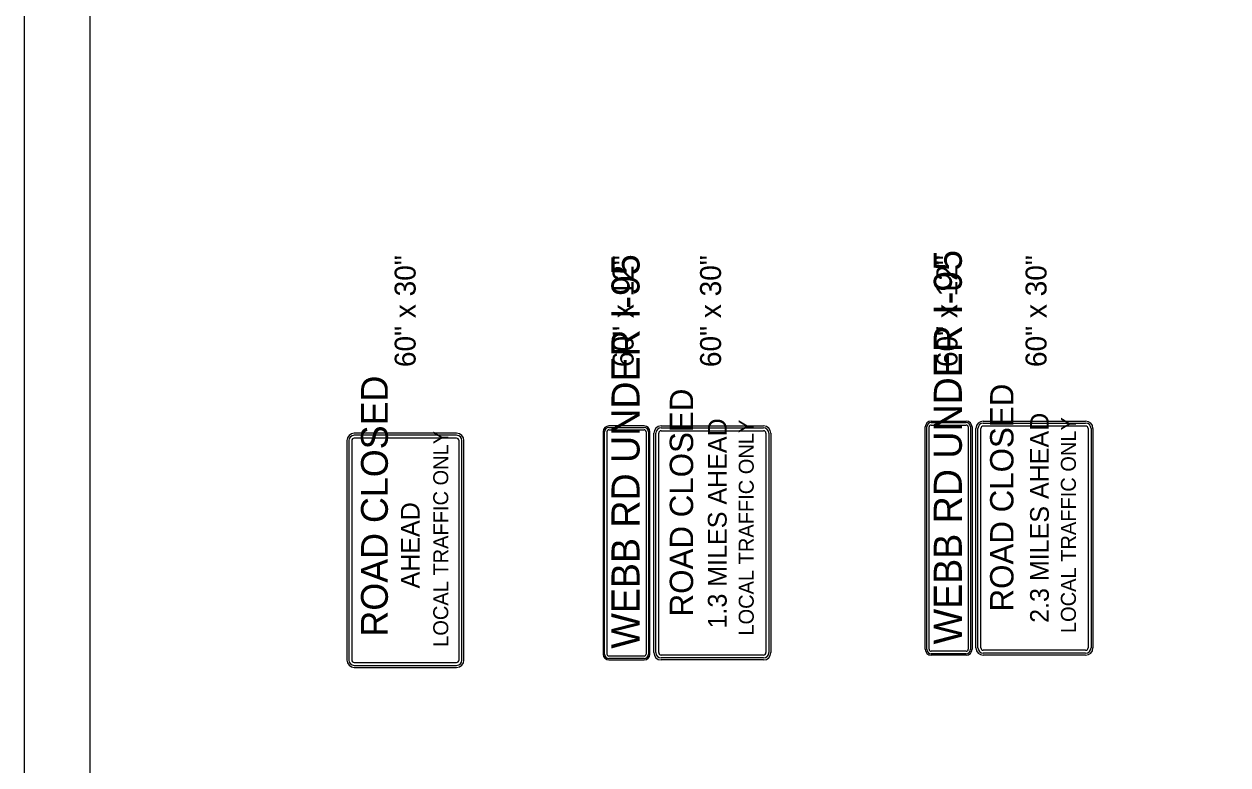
# Model space of a CAD drawing. Extents: x 1149904 to 1171904, y 589308 to 623636.
# Drawn here: x 1149904 to 1156977, y 601940 to 606292 of the extents above; entities that cross this region are included whole.
import ezdxf

# ---------------------------------------------------------------- set-up
doc = ezdxf.new("R2010")
doc.units = 0
for name, color, linetype in [('BORDER', 7, 'Continuous'), ('D_Text_Standard', 7, 'Continuous'), ('PLOT BOUNDARY', 7, 'Continuous'), ('SIGNS TRAFFIC', 7, 'Continuous')]:
    doc.layers.add(name, color=color, linetype=linetype)

msp = doc.modelspace()

# ---------------------------------------------------------------- linework, layer by layer
at = {"layer": 'BORDER'}
msp.add_lwpolyline([(1150292.4, 590926.2), (1150292.4, 622926.2), (1171292.4, 622926.2), (1171292.4, 590926.2)], close=True, dxfattribs=at)
at = {"layer": 'PLOT BOUNDARY'}
msp.add_lwpolyline([(1171904.3, 589307.6), (1171904.3, 623307.6), (1149904.3, 623307.6), (1149904.3, 589307.6)], close=True, dxfattribs=at)
at = {"layer": 'SIGNS TRAFFIC'}
for p, q in [((1155233.3, 603959.9), (1155439.5, 603959.9)), ((1155233.3, 603951.3), (1155439.5, 603951.3)), ((1155539.8, 603959.9), (1156141.3, 603959.9)), ((1152445.5, 603888.3), (1151843.9, 603888.3)), ((1153306.2, 603897.5), (1153306.2, 602591.2)), ((1153314.8, 602591.2), (1153314.8, 603897.5)), ((1153329.1, 602591.2), (1153329.1, 603897.5)), ((1153546.8, 603931.9), (1153340.5, 603931.9)), ((1153340.5, 603923.3), (1153546.8, 603923.3)), ((1153340.5, 603908.9), (1153546.8, 603908.9)), ((1153558.3, 603897.5), (1153558.3, 602591.2)), ((1153572.6, 603897.5), (1153572.6, 602591.2)), ((1153581.2, 602591.2), (1153581.2, 603897.5)), ((1153604.1, 602599.8), (1153604.1, 603888.9)), ((1153615.5, 602599.8), (1153615.5, 603888.9)), ((1153632.7, 602599.8), (1153632.7, 603888.9)), ((1153647.1, 603931.9), (1154248.6, 603931.9)), ((1153647.1, 603920.4), (1154248.6, 603920.4)), ((1153647.1, 603903.2), (1154248.6, 603903.2)), ((1154262.9, 603888.9), (1154262.9, 602599.8)), ((1154280.1, 603888.9), (1154280.1, 602599.8)), ((1154291.6, 603888.9), (1154291.6, 602599.8)), ((1155198.9, 602619.3), (1155198.9, 603925.5)), ((1155207.5, 602619.3), (1155207.5, 603925.5)), ((1155221.8, 602619.3), (1155221.8, 603925.5)), ((1155233.3, 603937), (1155439.5, 603937)), ((1155451, 603925.5), (1155451, 602619.3)), ((1155465.3, 603925.5), (1155465.3, 602619.3)), ((1155473.9, 603925.5), (1155473.9, 602619.3)), ((1155496.8, 602627.9), (1155496.8, 603916.9)), ((1155508.3, 602627.9), (1155508.3, 603916.9)), ((1155525.5, 602627.9), (1155525.5, 603916.9)), ((1155539.8, 603948.4), (1156141.3, 603948.4)), ((1155539.8, 603931.3), (1156141.3, 603931.3)), ((1156155.7, 603916.9), (1156155.7, 602627.9)), ((1156172.8, 603916.9), (1156172.8, 602627.9)), ((1156184.3, 603916.9), (1156184.3, 602627.9)), ((1151801, 603845.3), (1151801, 602556.3)), ((1151812.4, 603845.3), (1151812.4, 602556.3)), ((1151829.6, 603845.3), (1151829.6, 602556.3)), ((1152445.5, 603876.9), (1151843.9, 603876.9)), ((1152445.5, 603859.7), (1151843.9, 603859.7)), ((1152459.8, 602556.3), (1152459.8, 603845.3)), ((1152477, 602556.3), (1152477, 603845.3)), ((1152488.5, 602556.3), (1152488.5, 603845.3)), ((1155439.5, 602607.8), (1155233.3, 602607.8)), ((1156141.3, 602613.5), (1155539.8, 602613.5)), ((1151843.9, 602542), (1152445.5, 602542)), ((1153546.8, 602579.8), (1153340.5, 602579.8)), ((1153546.8, 602565.5), (1153340.5, 602565.5)), ((1153340.5, 602556.9), (1153546.8, 602556.9)), ((1154248.6, 602585.5), (1153647.1, 602585.5)), ((1154248.6, 602568.3), (1153647.1, 602568.3)), ((1154248.6, 602556.9), (1153647.1, 602556.9)), ((1155439.5, 602593.5), (1155233.3, 602593.5)), ((1155439.5, 602584.9), (1155233.3, 602584.9)), ((1156141.3, 602596.4), (1155539.8, 602596.4)), ((1156141.3, 602584.9), (1155539.8, 602584.9)), ((1151843.9, 602524.8), (1152445.5, 602524.8)), ((1151843.9, 602513.3), (1152445.5, 602513.3))]:
    msp.add_line(p, q, dxfattribs=at)
for centre, radius, start, end in [((1155233.3, 603925.5), 34.4, 90, 180), ((1155233.3, 603925.5), 25.8, 90, 180), ((1155439.5, 603925.5), 34.4, 0, 90), ((1155439.5, 603925.5), 25.8, 0, 90), ((1155539.8, 603916.9), 43, 90, 180), ((1156141.3, 603916.9), 43, 0, 90), ((1151843.9, 603845.3), 43, 90, 180), ((1152445.5, 603845.3), 43, 0, 90), ((1153340.5, 603897.5), 34.4, 90, 180), ((1153340.5, 603897.5), 25.8, 90, 180), ((1153340.5, 603897.5), 11.5, 90, 180), ((1153546.8, 603897.5), 34.4, 0, 90), ((1153546.8, 603897.5), 25.8, 0, 90), ((1153546.8, 603897.5), 11.5, 0, 90), ((1153647.1, 603888.9), 43, 90, 180), ((1153647.1, 603888.9), 31.5, 90, 180), ((1153647.1, 603888.9), 14.3, 90, 180), ((1154248.6, 603888.9), 43, 0, 90), ((1154248.6, 603888.9), 31.5, 0, 90), ((1154248.6, 603888.9), 14.3, 0, 90), ((1155233.3, 603925.5), 11.5, 90, 180), ((1155439.5, 603925.5), 11.5, 0, 90), ((1155539.8, 603916.9), 31.5, 90, 180), ((1155539.8, 603916.9), 14.3, 90, 180), ((1156141.3, 603916.9), 31.5, 0, 90), ((1156141.3, 603916.9), 14.3, 0, 90), ((1151843.9, 603845.3), 31.5, 90, 180), ((1151843.9, 603845.3), 14.3, 90, 180), ((1152445.5, 603845.3), 31.5, 0, 90), ((1152445.5, 603845.3), 14.3, 0, 90), ((1155233.3, 602619.3), 34.4, 180, 270), ((1155233.3, 602619.3), 25.8, 180, 270), ((1155233.3, 602619.3), 11.5, 180, 270), ((1155439.5, 602619.3), 34.4, 270, 0), ((1155439.5, 602619.3), 25.8, 270, 0), ((1155439.5, 602619.3), 11.5, 270, 0), ((1155539.8, 602627.9), 43, 180, 270), ((1155539.8, 602627.9), 31.5, 180, 270), ((1155539.8, 602627.9), 14.3, 180, 270), ((1156141.3, 602627.9), 43, 270, 0), ((1156141.3, 602627.9), 31.5, 270, 0), ((1156141.3, 602627.9), 14.3, 270, 0), ((1151843.9, 602556.3), 43, 180, 270), ((1151843.9, 602556.3), 31.5, 180, 270), ((1151843.9, 602556.3), 14.3, 180, 270), ((1152445.5, 602556.3), 43, 270, 0), ((1152445.5, 602556.3), 31.5, 270, 0), ((1152445.5, 602556.3), 14.3, 270, 0), ((1153340.5, 602591.2), 34.4, 180, 270), ((1153340.5, 602591.2), 25.8, 180, 270), ((1153340.5, 602591.2), 11.5, 180, 270), ((1153546.8, 602591.2), 34.4, 270, 0), ((1153546.8, 602591.2), 25.8, 270, 0), ((1153546.8, 602591.2), 11.5, 270, 0), ((1153647.1, 602599.8), 43, 180, 270), ((1153647.1, 602599.8), 31.5, 180, 270), ((1153647.1, 602599.8), 14.3, 180, 270), ((1154248.6, 602599.8), 43, 270, 0), ((1154248.6, 602599.8), 31.5, 270, 0), ((1154248.6, 602599.8), 14.3, 270, 0)]:
    msp.add_arc(centre, radius, start, end, dxfattribs=at)

# ---------------------------------------------------------------- texts
at = {"layer": 'D_Text_Standard'}
for s, p in [('60" x 30"', (1152204.7, 604277.2)), ('60" x 12"', (1153485.4, 604277.2)), ('60" x 30"', (1153999, 604277.2)), ('60" x 12"', (1155388.1, 604277.5)), ('60" x 30"', (1155911.4, 604277.5))]:
    msp.add_text(s, height=123.19, rotation=90, dxfattribs=at).set_placement(p)
at = {"layer": 'SIGNS TRAFFIC'}
for s, height, p in [('WEBB RD UNDER I-95', 165, (1155413.9, 602648.4)), ('WEBB RD UNDER I-95', 165, (1153520.3, 602623.3)), ('ROAD CLOSED', 157.5, (1152041.4, 602694.1)), ('ROAD CLOSED', 137.5, (1155717.3, 602841.5)), ('ROAD CLOSED', 137.5, (1153835.2, 602812.4)), ('1.3 MILES AHEAD', 110, (1154032.1, 602741.8)), ('LOCAL TRAFFIC ONLY', 88, (1154191.1, 602699.8)), ('2.3 MILES AHEAD', 110, (1155924.8, 602774.6)), ('LOCAL TRAFFIC ONLY', 88, (1156083.8, 602714.7)), ('LOCAL TRAFFIC ONLY', 88, (1152396.3, 602633.8)), ('AHEAD', 110, (1152227.9, 602976.8))]:
    msp.add_text(s, height=height, rotation=90, dxfattribs=at).set_placement(p)

doc.saveas('drawing.dxf')
